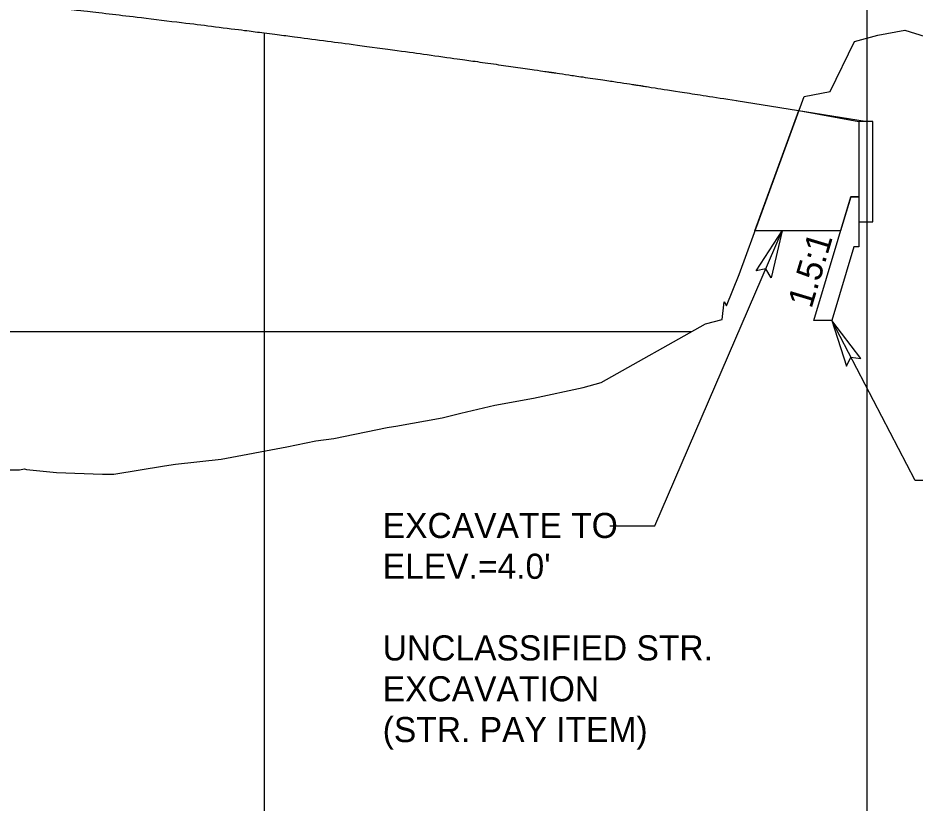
# Model space of a CAD drawing. Extents: x 1626634 to 1638383, y 876896 to 886347.
# Drawn here: x 1634281.8 to 1634460.4, y 884203.7 to 884360 of the extents above; entities that cross this region are included whole.
import ezdxf

# ---------------------------------------------------------------- set-up
doc = ezdxf.new("R2010")
doc.units = 0
for name, color, linetype in [('Exist Horizontal Alignment Tick Label', 7, 'Continuous'), ('Exist Vertical Profile Ground Line', 7, 'Continuous'), ('Prop CMT Undercut Boundary', 7, 'Continuous'), ('Sheet Block Title CELL', 7, 'Continuous'), ('Sheet Data Field CELL', 7, 'Continuous'), ('Sheet Profile Grid Major CELL', 7, 'Continuous'), ('Sheet Profile Grid Middle CELL', 7, 'Continuous'), ('Sheet Profile Grid Minor CELL', 7, 'Continuous'), ('Sheet Sticker Incomplete CELL', 7, 'Continuous'), ('Sheet Sticker Preliminary CELL', 7, 'Continuous')]:
    doc.layers.add(name, color=color, linetype=linetype)

msp = doc.modelspace()

# ---------------------------------------------------------------- linework, layer by layer
at = {"layer": 'Exist Vertical Profile Ground Line'}
msp.add_lwpolyline([(1634278.07, 884270.07), (1634282.13, 884270.06), (1634283.08, 884270.23), (1634283.5, 884270.16), (1634289.47, 884269.52), (1634298.61, 884269.23), (1634299.64, 884269.19), (1634300.92, 884269.22), (1634310.99, 884270.85), (1634313.2, 884271.2), (1634322.27, 884272.18), (1634335.32, 884274.65), (1634341.14, 884275.84), (1634344.7, 884276.28), (1634355.32, 884278.46), (1634355.72, 884278.53), (1634357.03, 884278.77), (1634366.29, 884280.44), (1634369.97, 884281.37), (1634376.75, 884282.9), (1634384.45, 884284.35), (1634394.34, 884286.44), (1634397.94, 884287.44), (1634418.72, 884299.15), (1634422.03, 884299.99), (1634422.39, 884303.49), (1634422.86, 884302.71), (1634425.37, 884308.95), (1634438.33, 884344.38), (1634443.5, 884345.35), (1634448.34, 884355.3), (1634452.97, 884356.57), (1634458.36, 884357.54), (1634462.45, 884356.29)], dxfattribs=at)
at = {"layer": 'Prop CMT Undercut Boundary'}
for p, q in [((1634408.62, 884258.91), (1634433.97, 884317.61)), ((1634399.62, 884258.91), (1634408.62, 884258.91))]:
    msp.add_line(p, q, dxfattribs=at)
at = {"layer": 'Sheet Block Title CELL'}
for points in [[(1634428.77, 884309.64), (1634433.97, 884317.61), (1634431.76, 884308.29), (1634430.71, 884310.05)], [(1634449.61, 884292.22), (1634443.86, 884299.79), (1634446.73, 884290.66), (1634447.65, 884292.49)]]:
    msp.add_lwpolyline(points, close=True, dxfattribs=at)
at = {"layer": 'Sheet Data Field CELL'}
for p, q in [((1634460.41, 884267.95), (1634443.86, 884299.79)), ((1634467.16, 884267.95), (1634460.41, 884267.95))]:
    msp.add_line(p, q, dxfattribs=at)
at = {"layer": 'Sheet Profile Grid Major CELL'}
msp.add_lwpolyline([(1634428.54, 884317.61), (1634437.3, 884341.57), (1634449.24, 884339.41), (1634449.24, 884324.41), (1634447.64, 884324.41), (1634445.6, 884317.61)], close=True, dxfattribs=at)
at = {"layer": 'Sheet Profile Grid Middle CELL'}
msp.add_line((1633526.8, 884297.61), (1634415.97, 884297.61), dxfattribs=at)
at = {"layer": 'Sheet Profile Grid Minor CELL'}
msp.add_lwpolyline([(1634447.64, 884324.41), (1634449.24, 884324.41), (1634449.24, 884314.41), (1634448.24, 884314.41), (1634443.86, 884299.79), (1634440.25, 884299.79)], close=True, dxfattribs=at)
at = {"layer": 'Sheet Sticker Incomplete CELL'}
for p, q in [((1634450.87, 884162.85), (1634450.87, 884371.37)), ((1634330.87, 884162.85), (1634330.87, 884357.02)), ((1634424.77, 884343.55), (1634450.87, 884339.41))]:
    msp.add_line(p, q, dxfattribs=at)
msp.add_lwpolyline([(1634449.24, 884319.41), (1634451.99, 884319.41), (1634451.99, 884339.41), (1634449.24, 884339.41)], close=True, dxfattribs=at)
msp.add_open_spline([(1633504.35, 884351.09), (1633509.17, 884351.76), (1633515.19, 884352.6), (1633521.36, 884353.46), (1633522.73, 884353.65), (1633522.91, 884353.67), (1633522.94, 884353.68), (1633522.96, 884353.68), (1633522.97, 884353.68), (1633523.01, 884353.69), (1633523.12, 884353.7), (1633523.52, 884353.76), (1633523.89, 884353.81), (1633524.76, 884353.93), (1633525.35, 884354.01), (1633528.28, 884354.41), (1633530.65, 884354.73), (1633535.4, 884355.35), (1633537.79, 884355.67), (1633540.5, 884356.02), (1633540.84, 884356.06), (1633541.19, 884356.11), (1633541.23, 884356.11), (1633541.25, 884356.12), (1633541.26, 884356.12), (1633541.29, 884356.12), (1633541.38, 884356.13), (1633541.63, 884356.17), (1633542.45, 884356.27), (1633544.38, 884356.52), (1633548.56, 884357.06), (1633552.14, 884357.52), (1633556.91, 884358.12), (1633559.3, 884358.42), (1633566.47, 884359.3), (1633571.24, 884359.88), (1633580.8, 884361.02), (1633585.58, 884361.57), (1633592.75, 884362.39), (1633595.14, 884362.66), (1633599.92, 884363.2), (1633602.32, 884363.46), (1633609.49, 884364.25), (1633614.27, 884364.76), (1633621.45, 884365.52), (1633625.04, 884365.89), (1633628.63, 884366.25), (1633631.03, 884366.5), (1633632.22, 884366.62), (1633638.21, 884367.22), (1633643, 884367.68), (1633650.18, 884368.37), (1633652.58, 884368.6), (1633657.37, 884369.04), (1633662.16, 884369.48), (1633666.95, 884369.91), (1633671.74, 884370.33), (1633674.14, 884370.54), (1633681.33, 884371.16), (1633686.13, 884371.56), (1633695.72, 884372.34), (1633700.51, 884372.72), (1633710.11, 884373.46), (1633714.91, 884373.81), (1633722.11, 884374.33), (1633724.51, 884374.5), (1633729.31, 884374.84), (1633731.71, 884375), (1633738.91, 884375.48), (1633743.71, 884375.8), (1633750.91, 884376.25), (1633753.31, 884376.39), (1633758.11, 884376.68), (1633760.52, 884376.82), (1633772.52, 884377.52), (1633782.13, 884378.03), (1633796.55, 884378.72), (1633801.36, 884378.94), (1633810.97, 884379.36), (1633815.78, 884379.56), (1633825.39, 884379.94), (1633830.2, 884380.11), (1633839.82, 884380.44), (1633844.62, 884380.59), (1633854.24, 884380.88), (1633859.05, 884381.01), (1633868.67, 884381.25), (1633873.48, 884381.35), (1633883.1, 884381.55), (1633887.91, 884381.63), (1633897.53, 884381.78), (1633902.34, 884381.84), (1633916.77, 884381.99), (1633926.4, 884382.05), (1633945.64, 884382.07), (1633955.26, 884382.04), (1633969.69, 884381.92), (1633974.51, 884381.87), (1633984.13, 884381.74), (1633988.94, 884381.67), (1633998.56, 884381.5), (1634003.37, 884381.4), (1634012.99, 884381.19), (1634017.8, 884381.07), (1634027.42, 884380.81), (1634032.22, 884380.66), (1634041.84, 884380.36), (1634046.65, 884380.19), (1634056.27, 884379.84), (1634061.07, 884379.65), (1634070.69, 884379.26), (1634075.49, 884379.05), (1634085.11, 884378.6), (1634089.91, 884378.37), (1634099.52, 884377.88), (1634104.33, 884377.63), (1634113.93, 884377.09), (1634118.74, 884376.82), (1634128.34, 884376.24), (1634133.14, 884375.94), (1634142.75, 884375.31), (1634147.55, 884374.99), (1634157.15, 884374.32), (1634161.94, 884373.98), (1634169.14, 884373.44), (1634171.54, 884373.26), (1634176.34, 884372.89), (1634178.74, 884372.71), (1634185.93, 884372.14), (1634190.73, 884371.75), (1634197.92, 884371.15), (1634200.32, 884370.94), (1634205.11, 884370.53), (1634207.51, 884370.32), (1634214.7, 884369.68), (1634219.49, 884369.25), (1634229.07, 884368.36), (1634233.86, 884367.9), (1634241.04, 884367.2), (1634243.44, 884366.96), (1634248.23, 884366.48), (1634250.62, 884366.24), (1634255.41, 884365.75), (1634257.8, 884365.5), (1634262.58, 884365), (1634267.37, 884364.49), (1634272.15, 884363.97), (1634276.94, 884363.45), (1634279.33, 884363.18), (1634284.11, 884362.65), (1634287.7, 884362.24), (1634291.28, 884361.83), (1634293.67, 884361.55), (1634294.87, 884361.41), (1634300.84, 884360.72), (1634305.62, 884360.15), (1634315.17, 884358.99), (1634319.95, 884358.4), (1634327.11, 884357.5), (1634329.5, 884357.19), (1634334.27, 884356.58), (1634336.66, 884356.27), (1634343.81, 884355.34), (1634348.58, 884354.7), (1634358.12, 884353.41), (1634362.89, 884352.75), (1634370.04, 884351.75), (1634372.42, 884351.42), (1634377.19, 884350.74), (1634380.76, 884350.22), (1634384.93, 884349.62), (1634386.86, 884349.34), (1634387.64, 884349.22), (1634387.83, 884349.19), (1634387.9, 884349.18), (1634387.94, 884349.18), (1634388.05, 884349.16), (1634388.43, 884349.11), (1634388.8, 884349.05), (1634391.5, 884348.65), (1634393.89, 884348.3), (1634398.63, 884347.6), (1634400.99, 884347.25), (1634403.92, 884346.8), (1634404.5, 884346.71), (1634405.38, 884346.57), (1634405.74, 884346.52), (1634406.12, 884346.46), (1634406.22, 884346.44), (1634406.25, 884346.44), (1634406.27, 884346.43), (1634406.28, 884346.43), (1634406.33, 884346.43), (1634406.51, 884346.4), (1634407.9, 884346.18), (1634414.06, 884345.22), (1634420.06, 884344.29), (1634424.87, 884343.54)], degree=3, dxfattribs=at)
at = {"layer": 'Sheet Sticker Preliminary CELL'}
for p, q in [((1634439.59, 884317.61), (1634428.54, 884317.61)), ((1634443.86, 884299.79), (1634440.25, 884299.79))]:
    msp.add_line(p, q, dxfattribs=at)
msp.add_lwpolyline([(1634440.25, 884299.79), (1634447.64, 884324.41), (1634449.24, 884324.41), (1634449.24, 884314.41), (1634448.24, 884314.41), (1634443.86, 884299.79)], dxfattribs=at)

# ---------------------------------------------------------------- texts
at = {"layer": 'Exist Horizontal Alignment Tick Label'}
msp.add_text('1.5:1', height=5, rotation=73.3008, dxfattribs=at).set_placement((1634439.78, 884302.01))
at = {"layer": 'Prop CMT Undercut Boundary'}
for s, p in [('EXCAVATE TO', (1634354.42, 884256.49)), ("ELEV.=4.0'", (1634354.42, 884248.37)), ('UNCLASSIFIED STR.', (1634354.42, 884232.12)), ('EXCAVATION', (1634354.42, 884223.99)), ('(STR. PAY ITEM)', (1634354.42, 884215.87))]:
    msp.add_text(s, height=5, dxfattribs=at).set_placement(p)

doc.saveas('drawing.dxf')
